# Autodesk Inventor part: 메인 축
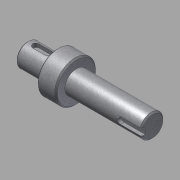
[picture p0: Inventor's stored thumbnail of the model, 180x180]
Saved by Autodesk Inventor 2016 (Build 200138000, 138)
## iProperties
Created: 2014-10
Part Number: 메인 축
Document SubType Name: Modeling
Designer: KYOUNG IL JANG
Density: 7.86 g/cm^3
Mass: 230.24 g
Surface Area: 74.3518 cm^2
Volume: 29.2926 cm^3
Material: 강철, 연강
Appearance: 금속-강(스테인리스, 브러시됨)
Author: SeoGD™ [www.esajin.kr]
Revision Number: 1
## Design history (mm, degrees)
sketch "스케치1"
  geometry: L1 (10.497, -57.5)-(102.497, -57.5); L2 (10.497, -66)-(32.497, -66); L3 (32.497, -72.5)-(46.5, -72.5); L4 (46.5, -66)-(102.497, -66); L5 (102.497, -66)-(102.497, -57.5); L6 (10.497, -66)-(10.497, -57.5); L7 (46.5, -69.749)-(46.5, -45.251) reference; L8 (46.5, -72.5)-(46.5, -66); L9 (32.497, -72.5)-(32.497, -66); L10 (32.497, -35)-(32.497, -80) reference; 2 further points
  constraints: 16 end point, 2 parallel, 2 perpendicular, 2 point on line, 1 collinear, 1 horizontal, 1 midpoint
  dimensions: "d0" = 17 diameter of L4 L1; "d1" = 30 diameter of L3 L1; "d2" = 22 distance of L2.start L2.end; "d3" = 55.99692 distance of L4.start L4.end (derived); "d5" = 17 diameter of L2 L1; "d19" = 70 distance between parallel lines of L5 L9
revolve "회전1" sketch "스케치1" stored, may be unused: angle "d4" = 90 deg
chamfer "모따기1" distance "d6" = 1; stored, may be unused: second distance "d7" = 2, angle "d8" = 45 deg
node "작업 평면1"
sketch "스케치2"
  geometry: L1 (-11, -7.5)-(-11, 7.5) reference; L2 (-4.5, 2.5)-(4.5, 2.5); L3 (4.5, -2.5)-(-4.5, -2.5); A1 r 2.5 centre (4.5, 0) between (4.5, -2.5) and (4.5, 2.5); A2 r 2.5 centre (-4.5, 0) between (-4.5, 2.5) and (-4.5, -2.5); 2 further points
  constraints: 4 end point, 4 point on circle, 4 tangent, 2 centre point, 1 horizontal alignment, 1 midpoint, 1 parallel, 1 perpendicular
  dimensions: "d9" = 5 distance between parallel lines of L3 L2; "d10" = 14 dimension on A1 A2; "d11" = 4 distance edge to line of A2 L1
extrude "돌출1" cut sketch "스케치2" distance "d12" = 3; taper "d13" = 0 deg
node "작업 평면2"
sketch "스케치3"
  geometry: L1 (27.998, 7.5)-(27.998, -7.5) reference; L2 (27.998, 2.5)-(12.498, 2.5); L3 (12.498, -2.5)-(27.998, -2.5); A1 r 2.5 centre (12.498, 0) between (12.498, 2.5) and (12.498, -2.5); 2 further points
  constraints: 4 end point, 2 perpendicular, 2 point on circle, 2 point on line, 2 tangent, 1 centre point, 1 horizontal alignment, 1 midpoint
  dimensions: "d14" = 5 distance between parallel lines of L3 L2; "d15" = 18 dimension on A1 L1
extrude "돌출2" cut sketch "스케치3" distance "d16" = 3; taper "d17" = 0 deg
node "솔리드1"
node "참조4"
node "참조5"
